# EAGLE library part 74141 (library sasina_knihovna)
Dekoder BCD - 1 z 10 s vystupy pro rizeni digitronu.
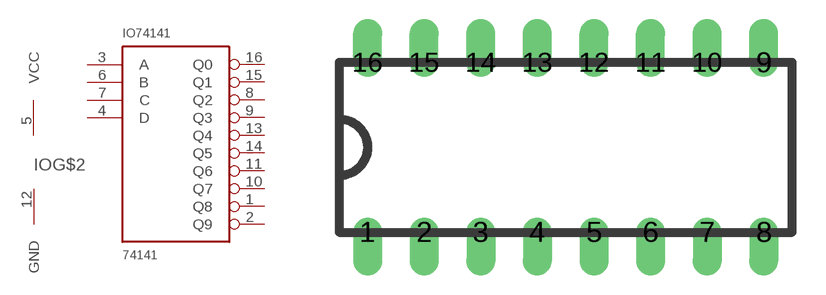
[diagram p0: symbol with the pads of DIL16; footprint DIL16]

Designator prefix IO; gates 74141=74141 G$2=NAPAJENI

## 74141N  [DIL16]
1  74141:Q8  oc
2  74141:Q9  oc
3  74141:A  in
4  74141:D  in
5  G$2:VCC  pwr
6  74141:B  in
7  74141:C  in
8  74141:Q2  oc
9  74141:Q3  oc
10  74141:Q7  oc
11  74141:Q6  oc
12  G$2:GND  pwr
13  74141:Q4  oc
14  74141:Q5  oc
15  74141:Q1  oc
16  74141:Q0  oc

## Footprint DIL16 (pad centres in mm)
drill 0.8 offset: 1 0,-1.27; 2 2.54,-1.27; 3 5.08,-1.27; 4 7.62,-1.27; 5 10.16,-1.27; 6 12.7,-1.27; 7 15.24,-1.27; 8 17.78,-1.27; 9 17.78,6.35; 10 15.24,6.35; 11 12.7,6.35; 12 10.16,6.35; 13 7.62,6.35; 14 5.08,6.35; 15 2.54,6.35; 16 0,6.35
